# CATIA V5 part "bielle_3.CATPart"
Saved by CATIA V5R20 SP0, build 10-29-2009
Part number: sqlt_bielle_3
Publications: "longueur_bielle_3", "rayon_pivot_bielle", "rayon_pivot_bati", "épaisseur_piece", "Plan.1", "Point.1", "Droite.1", "Point.2", "Point.4", "Point.5", "Point.6", "Droite.2", "Droite.3", "Plan.2", "Plan.3"
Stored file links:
  D:\ecole\thinkmotion\IAO\bielle_3.CATPart
  D:\ecole\thinkmotion\IAO\bielle_1.CATPart
  D:\ecole\thinkmotion\IAO\sqlt mecanisme coulisseau.CATProduct
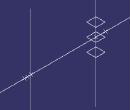
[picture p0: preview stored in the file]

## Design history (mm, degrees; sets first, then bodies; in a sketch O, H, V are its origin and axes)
Parameters
  longueur_bielle_3 = 100 mm {= External.longueur_bielle_3}
  rayon_pivot_bielle = 5 mm {= External.rayon_pivot_bielle}
  rayon_pivot_bati = 10 mm {= External.rayon_pivot_bati}
  `épaisseur_piece` = 20 mm {= `External.épaisseur_piece`}
External parameters (linked from other documents)
  External.longueur_bielle_3 = 100 mm
  External.rayon_pivot_bielle = 5 mm
  External.rayon_pivot_bati = 10 mm
  `External.épaisseur_piece` = 20 mm
Set1 "sqlt_bielle_3"
  Plane1: type Offset, RefPlane xy-plane, Offset 0
  Point1: (0, 0, 0)
  Line1: type PtDir, RefPoint Point1, Direction yz-plane, Start 0, End 20
  Point2: type OnCurve, Support Line1, Length 100 {= longueur_bielle_3}
  Point3: (-15 {= -rayon_pivot_bati -5mm}, 0, 0)
  Point4: (5 {= rayon_pivot_bielle}, 0, 0), relative to Point2
  Point5: (10 {= rayon_pivot_bielle +5mm}, 0, 0), relative to Point2
  Line2: type PtDir, RefPoint Point1, Direction Plane1, Start 0, End 20
  Line3: type PtDir, RefPoint Point2, Direction Plane1, Start 0, End 20
  Plane2: type Offset, RefPlane xy-plane, Offset 20 {= `épaisseur_piece`}
  Plane3: type Offset, RefPlane xy-plane, Offset 20 {= `épaisseur_piece`}, reversed
Body1 (main body)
